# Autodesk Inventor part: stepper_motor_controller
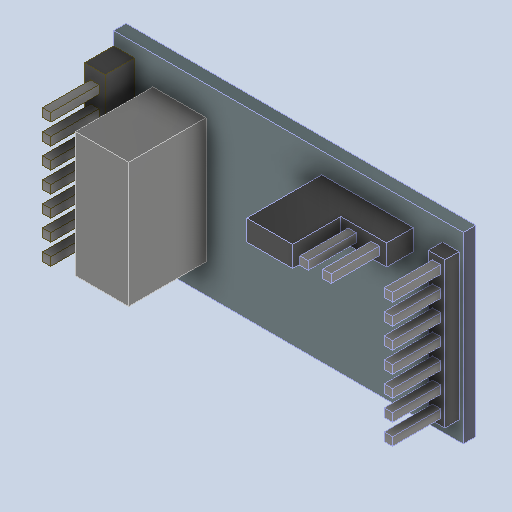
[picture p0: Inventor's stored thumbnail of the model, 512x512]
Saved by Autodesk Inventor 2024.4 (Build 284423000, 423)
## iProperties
Created: 2025-07
Part Number: stepper_motor_controller
Material: Generic
Document SubType Name: Modeling
Designer: AdminForWorker
Density: 1 g/cm^3
Appearance: Default
Title: stepper_motor_controller v2
Author: AdminForWorker
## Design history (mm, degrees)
feature "Body1"
feature "Body2"
feature "Body4"
body "Solid1"
body "Solid2"
body "Solid3"
